// Mitsubishi GX Works2 project: L系列PLC与BD45XX通信例程   PLC: L02

PROGRAM MAIN
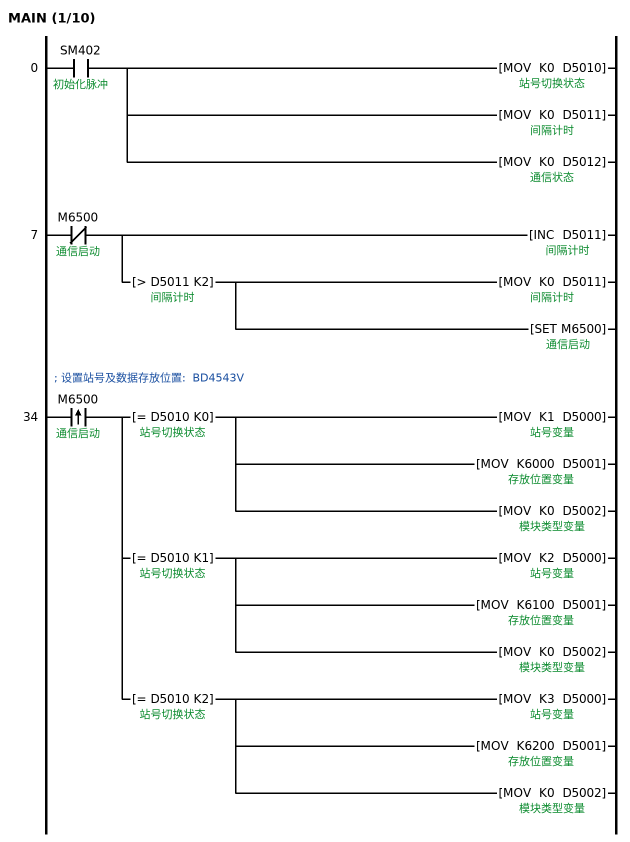
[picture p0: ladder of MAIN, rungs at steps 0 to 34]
0     LD      SM402  ; 初始化脉冲
      MOV     K0 D5010  ; 站号切换状态
      MOV     K0 D5011  ; 间隔计时
      MOV     K0 D5012  ; 通信状态
7     LDI     M6500  ; 通信启动
      INC     D5011
      AND>    D5011 K2  ; 间隔计时
      MOV     K0 D5011
      SET     M6500  ; 通信启动
; 设置站号及数据存放位置:  BD4543V
34    LDP     M6500  ; 通信启动
      MPS
      AND=    D5010 K0  ; 站号切换状态
      MOV     K1 D5000  ; 站号变量
      MOV     K6000 D5001  ; 存放位置变量
      MOV     K0 D5002  ; 模块类型变量
      MRD
      AND=    D5010 K1  ; 站号切换状态
      MOV     K2 D5000
      MOV     K6100 D5001
      MOV     K0 D5002
      MPP
      AND=    D5010 K2  ; 站号切换状态
      MOV     K3 D5000
      MOV     K6200 D5001
      MOV     K0 D5002
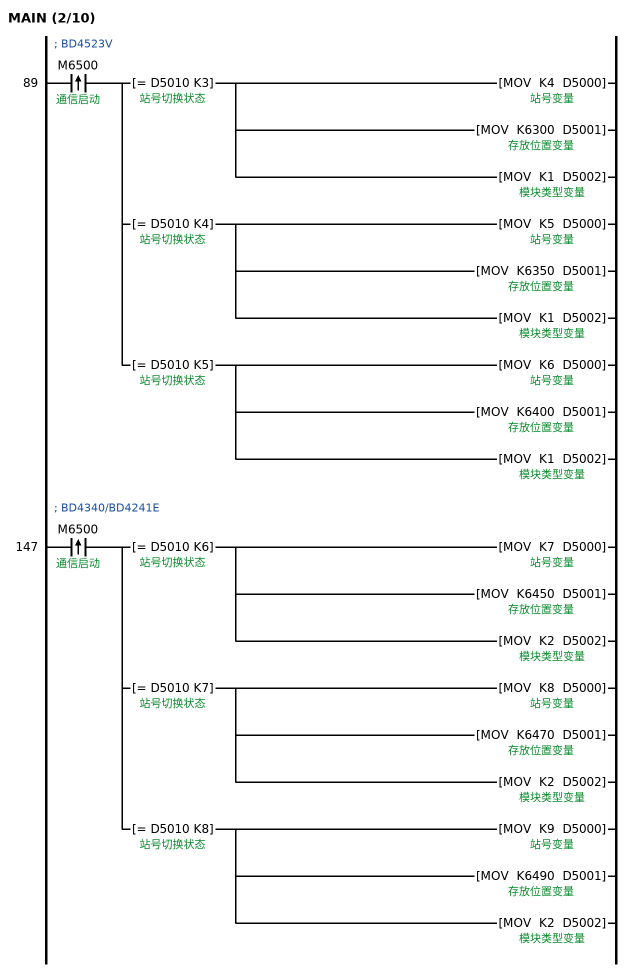
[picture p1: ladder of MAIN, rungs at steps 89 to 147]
; BD4523V
89    LDP     M6500  ; 通信启动
      MPS
      AND=    D5010 K3  ; 站号切换状态
      MOV     K4 D5000
      MOV     K6300 D5001
      MOV     K1 D5002
      MRD
      AND=    D5010 K4  ; 站号切换状态
      MOV     K5 D5000
      MOV     K6350 D5001
      MOV     K1 D5002
      MPP
      AND=    D5010 K5  ; 站号切换状态
      MOV     K6 D5000
      MOV     K6400 D5001
      MOV     K1 D5002
; BD4340/BD4241E
147   LDP     M6500  ; 通信启动
      MPS
      AND=    D5010 K6  ; 站号切换状态
      MOV     K7 D5000
      MOV     K6450 D5001
      MOV     K2 D5002
      MRD
      AND=    D5010 K7  ; 站号切换状态
      MOV     K8 D5000
      MOV     K6470 D5001
      MOV     K2 D5002
      MPP
      AND=    D5010 K8  ; 站号切换状态
      MOV     K9 D5000
      MOV     K6490 D5001
      MOV     K2 D5002
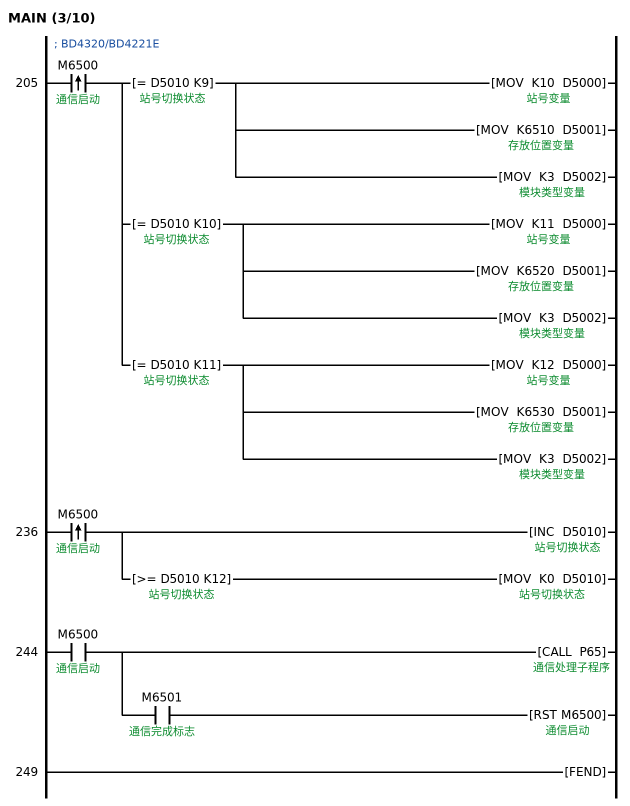
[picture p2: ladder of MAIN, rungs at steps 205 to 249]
; BD4320/BD4221E
205   LDP     M6500  ; 通信启动
      MPS
      AND=    D5010 K9  ; 站号切换状态
      MOV     K10 D5000
      MOV     K6510 D5001
      MOV     K3 D5002
      MRD
      AND=    D5010 K10  ; 站号切换状态
      MOV     K11 D5000
      MOV     K6520 D5001
      MOV     K3 D5002
      MPP
      AND=    D5010 K11  ; 站号切换状态
      MOV     K12 D5000
      MOV     K6530 D5001
      MOV     K3 D5002
236   LDP     M6500  ; 通信启动
      INC     D5010
      AND>=   D5010 K12  ; 站号切换状态
      MOV     K0 D5010
244   LD      M6500  ; 通信启动
      CALL    P65  ; 通信处理子程序
      AND     M6501  ; 通信完成标志
      RST     M6500  ; 通信启动
249   FEND
      P65
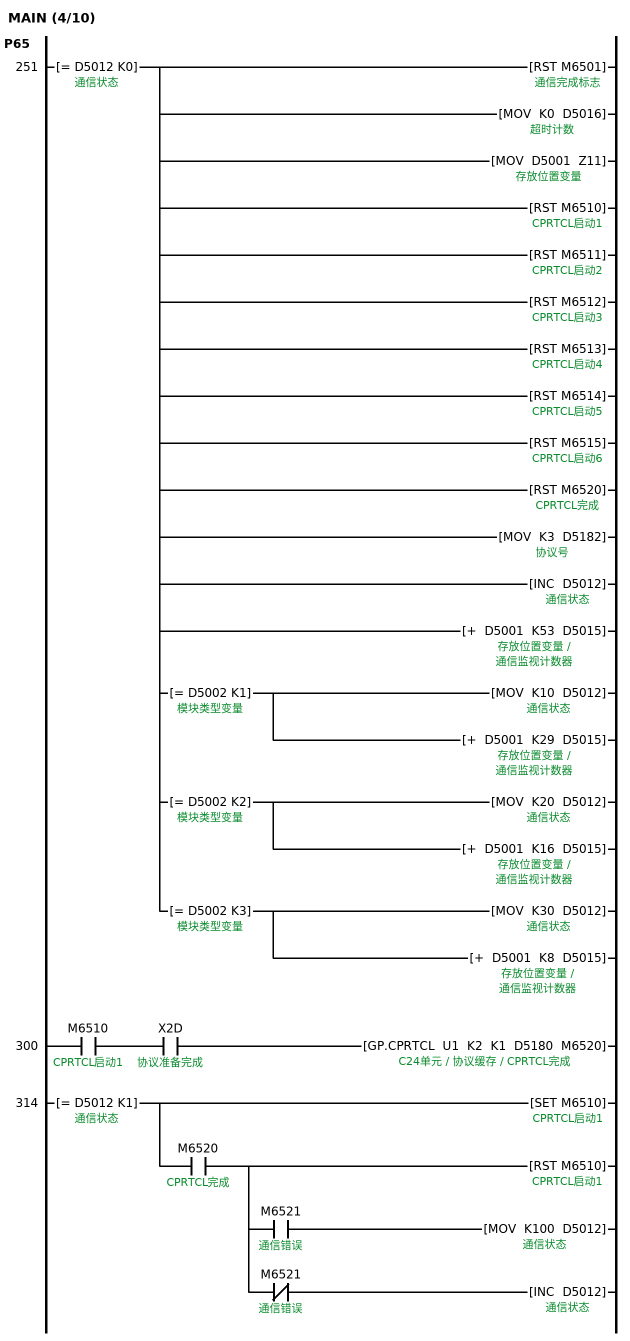
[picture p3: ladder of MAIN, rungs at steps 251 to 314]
251   LD=     D5012 K0  ; 通信状态
      RST     M6501  ; 通信完成标志
      MOV     K0 D5016  ; 超时计数
      MOV     D5001 Z11
      RST     M6510  ; CPRTCL启动1
      RST     M6511  ; CPRTCL启动2
      RST     M6512  ; CPRTCL启动3
      RST     M6513  ; CPRTCL启动4
      RST     M6514  ; CPRTCL启动5
      RST     M6515  ; CPRTCL启动6
      RST     M6520  ; CPRTCL完成
      MOV     K3 D5182  ; 协议号
      INC     D5012
      +       D5001 K53 D5015  ; 通信监视计数器
      MPS
      AND=    D5002 K1  ; 模块类型变量
      MOV     K10 D5012
      +       D5001 K29 D5015
      MRD
      AND=    D5002 K2  ; 模块类型变量
      MOV     K20 D5012
      +       D5001 K16 D5015
      MPP
      AND=    D5002 K3  ; 模块类型变量
      MOV     K30 D5012
      +       D5001 K8 D5015
300   LD      M6510  ; CPRTCL启动1
      AND     X2D  ; 协议准备完成
      GP.CPRTCL U1 K2 K1 D5180 M6520  ; C24单元 / 协议缓存
314   LD=     D5012 K1  ; 通信状态
      SET     M6510  ; CPRTCL启动1
      AND     M6520  ; CPRTCL完成
      RST     M6510  ; CPRTCL启动1
      MPS
      AND     M6521  ; 通信错误
      MOV     K100 D5012
      MPP
      ANI     M6521  ; 通信错误
      INC     D5012
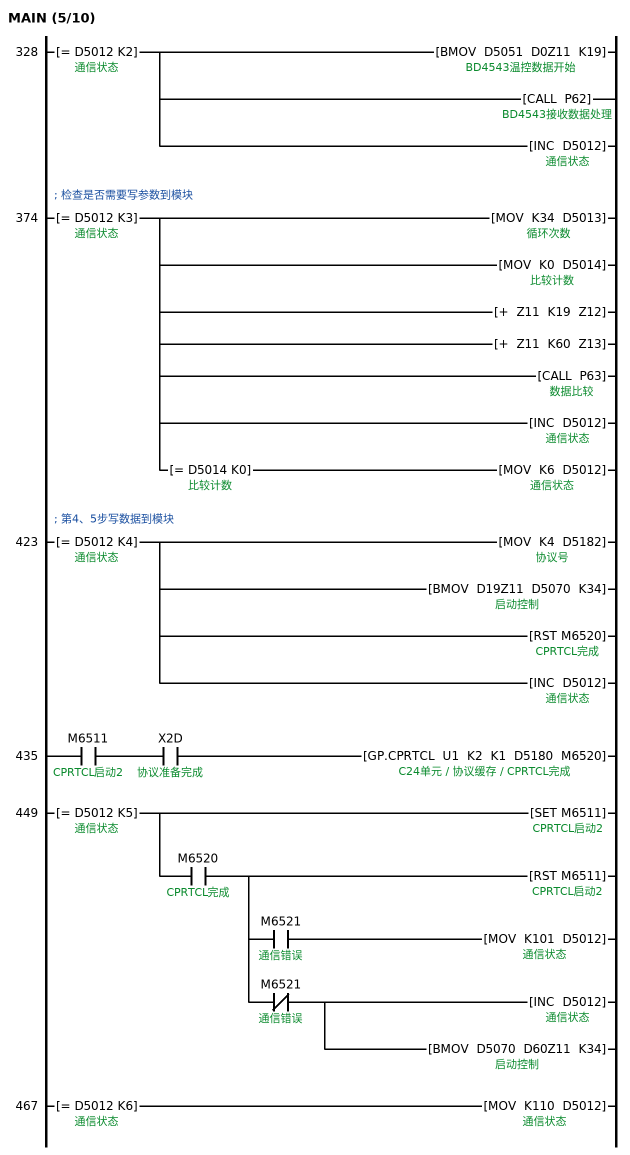
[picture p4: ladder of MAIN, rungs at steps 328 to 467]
328   LD=     D5012 K2  ; 通信状态
      BMOV    D5051 D0Z11 K19  ; BD4543温控数据开始
        [note] 数据处理
      CALL    P62  ; BD4543接收数据处理
      INC     D5012
; 检查是否需要写参数到模块
374   LD=     D5012 K3  ; 通信状态
      MOV     K34 D5013  ; 循环次数
      MOV     K0 D5014  ; 比较计数
      +       Z11 K19 Z12
      +       Z11 K60 Z13
      CALL    P63  ; 数据比较
      INC     D5012
      AND=    D5014 K0  ; 比较计数
      MOV     K6 D5012
; 第4、5步写数据到模块
423   LD=     D5012 K4  ; 通信状态
      MOV     K4 D5182
      BMOV    D19Z11 D5070 K34  ; 启动控制
      RST     M6520  ; CPRTCL完成
      INC     D5012
435   LD      M6511  ; CPRTCL启动2
      AND     X2D  ; 协议准备完成
      GP.CPRTCL U1 K2 K1 D5180 M6520
449   LD=     D5012 K5  ; 通信状态
      SET     M6511  ; CPRTCL启动2
      AND     M6520  ; CPRTCL完成
      RST     M6511  ; CPRTCL启动2
      MPS
      AND     M6521  ; 通信错误
      MOV     K101 D5012
      MPP
      ANI     M6521  ; 通信错误
      INC     D5012
      BMOV    D5070 D60Z11 K34
467   LD=     D5012 K6  ; 通信状态
      MOV     K110 D5012
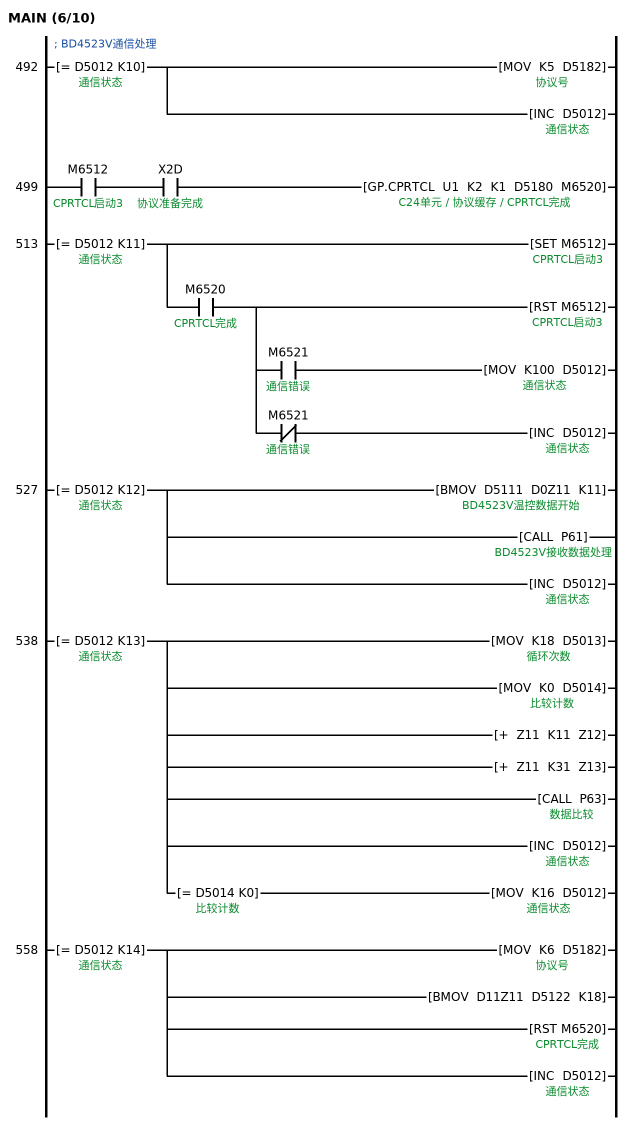
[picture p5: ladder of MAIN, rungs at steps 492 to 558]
; BD4523V通信处理
492   LD=     D5012 K10  ; 通信状态
      MOV     K5 D5182
      INC     D5012
499   LD      M6512  ; CPRTCL启动3
      AND     X2D  ; 协议准备完成
      GP.CPRTCL U1 K2 K1 D5180 M6520
513   LD=     D5012 K11  ; 通信状态
      SET     M6512  ; CPRTCL启动3
      AND     M6520  ; CPRTCL完成
      RST     M6512  ; CPRTCL启动3
      MPS
      AND     M6521  ; 通信错误
      MOV     K100 D5012
      MPP
      ANI     M6521  ; 通信错误
      INC     D5012
527   LD=     D5012 K12  ; 通信状态
      BMOV    D5111 D0Z11 K11  ; BD4523V温控数据开始
      CALL    P61  ; BD4523V接收数据处理
      INC     D5012
538   LD=     D5012 K13  ; 通信状态
      MOV     K18 D5013
      MOV     K0 D5014
      +       Z11 K11 Z12
      +       Z11 K31 Z13
      CALL    P63
      INC     D5012
      AND=    D5014 K0  ; 比较计数
      MOV     K16 D5012
558   LD=     D5012 K14  ; 通信状态
      MOV     K6 D5182
      BMOV    D11Z11 D5122 K18
      RST     M6520  ; CPRTCL完成
      INC     D5012
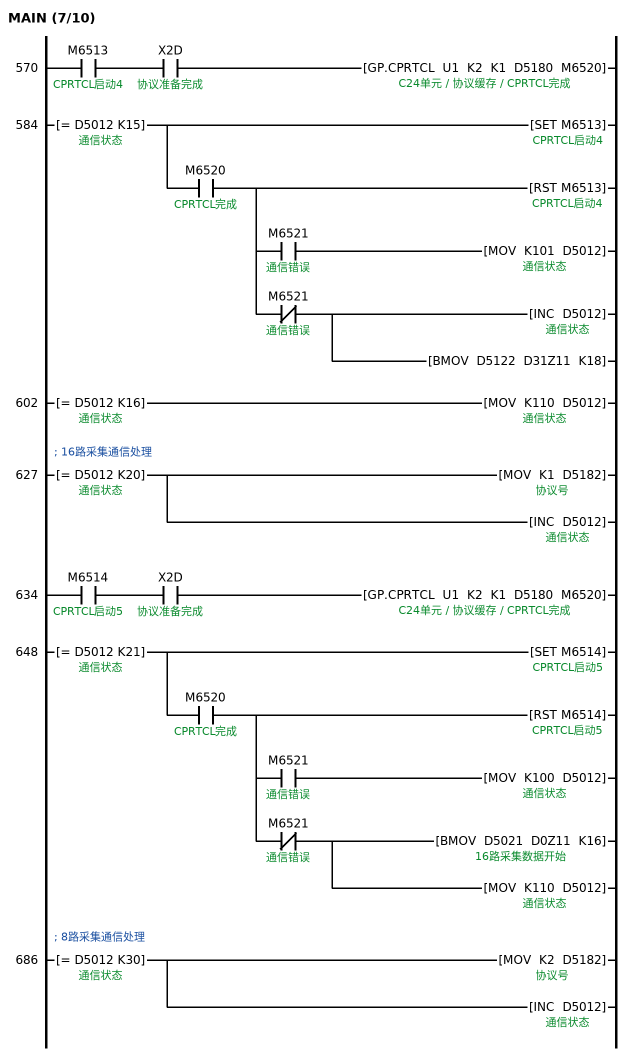
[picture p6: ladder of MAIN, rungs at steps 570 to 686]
570   LD      M6513  ; CPRTCL启动4
      AND     X2D  ; 协议准备完成
      GP.CPRTCL U1 K2 K1 D5180 M6520
584   LD=     D5012 K15  ; 通信状态
      SET     M6513  ; CPRTCL启动4
      AND     M6520  ; CPRTCL完成
      RST     M6513  ; CPRTCL启动4
      MPS
      AND     M6521  ; 通信错误
      MOV     K101 D5012
      MPP
      ANI     M6521  ; 通信错误
      INC     D5012
      BMOV    D5122 D31Z11 K18
602   LD=     D5012 K16  ; 通信状态
      MOV     K110 D5012
; 16路采集通信处理
627   LD=     D5012 K20  ; 通信状态
      MOV     K1 D5182
      INC     D5012
634   LD      M6514  ; CPRTCL启动5
      AND     X2D  ; 协议准备完成
      GP.CPRTCL U1 K2 K1 D5180 M6520
648   LD=     D5012 K21  ; 通信状态
      SET     M6514  ; CPRTCL启动5
      AND     M6520  ; CPRTCL完成
      RST     M6514  ; CPRTCL启动5
      MPS
      AND     M6521  ; 通信错误
      MOV     K100 D5012
      MPP
      ANI     M6521  ; 通信错误
      BMOV    D5021 D0Z11 K16  ; 16路采集数据开始
      MOV     K110 D5012
; 8路采集通信处理
686   LD=     D5012 K30  ; 通信状态
      MOV     K2 D5182
      INC     D5012
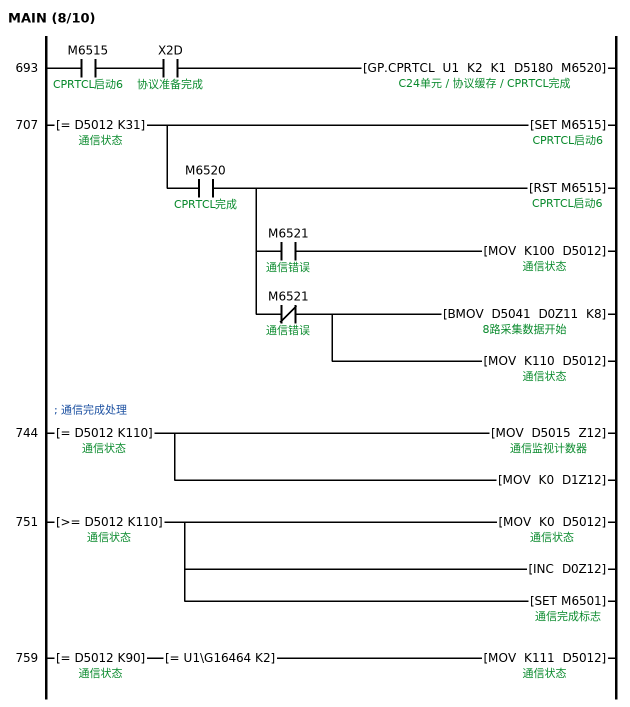
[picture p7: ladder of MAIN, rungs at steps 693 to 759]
693   LD      M6515  ; CPRTCL启动6
      AND     X2D  ; 协议准备完成
      GP.CPRTCL U1 K2 K1 D5180 M6520
707   LD=     D5012 K31  ; 通信状态
      SET     M6515  ; CPRTCL启动6
      AND     M6520  ; CPRTCL完成
      RST     M6515  ; CPRTCL启动6
      MPS
      AND     M6521  ; 通信错误
      MOV     K100 D5012
      MPP
      ANI     M6521  ; 通信错误
      BMOV    D5041 D0Z11 K8  ; 8路采集数据开始
      MOV     K110 D5012
; 通信完成处理
744   LD=     D5012 K110  ; 通信状态
      MOV     D5015 Z12
      MOV     K0 D1Z12
751   LD>=    D5012 K110  ; 通信状态
      MOV     K0 D5012
      INC     D0Z12
      SET     M6501  ; 通信完成标志
759   LD=     D5012 K90  ; 通信状态
      AND=    U1\G16464 K2
      MOV     K111 D5012
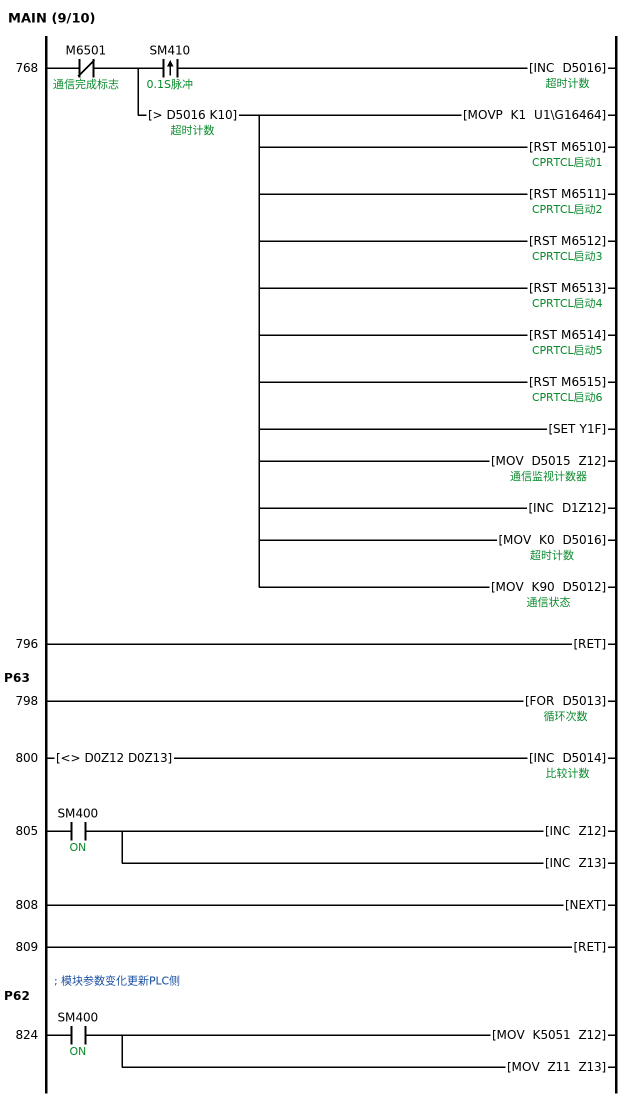
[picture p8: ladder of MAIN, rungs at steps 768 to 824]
768   LDI     M6501  ; 通信完成标志
      MPS
      ANDP    SM410  ; 0.1S脉冲
      INC     D5016
      MPP
      AND>    D5016 K10  ; 超时计数
      MOVP    K1 U1\G16464
      RST     M6510  ; CPRTCL启动1
      RST     M6511  ; CPRTCL启动2
      RST     M6512  ; CPRTCL启动3
      RST     M6513  ; CPRTCL启动4
      RST     M6514  ; CPRTCL启动5
      RST     M6515  ; CPRTCL启动6
      SET     Y1F
      MOV     D5015 Z12
      INC     D1Z12
      MOV     K0 D5016
      MOV     K90 D5012
796   RET
      P63
798   FOR     D5013
800   LD<>    D0Z12 D0Z13
      INC     D5014
805   LD      SM400  ; ON
      INC     Z12
      INC     Z13
808   NEXT
809   RET
; 模块参数变化更新PLC侧
      P62
824   LD      SM400  ; ON
      MOV     K5051 Z12
      MOV     Z11 Z13
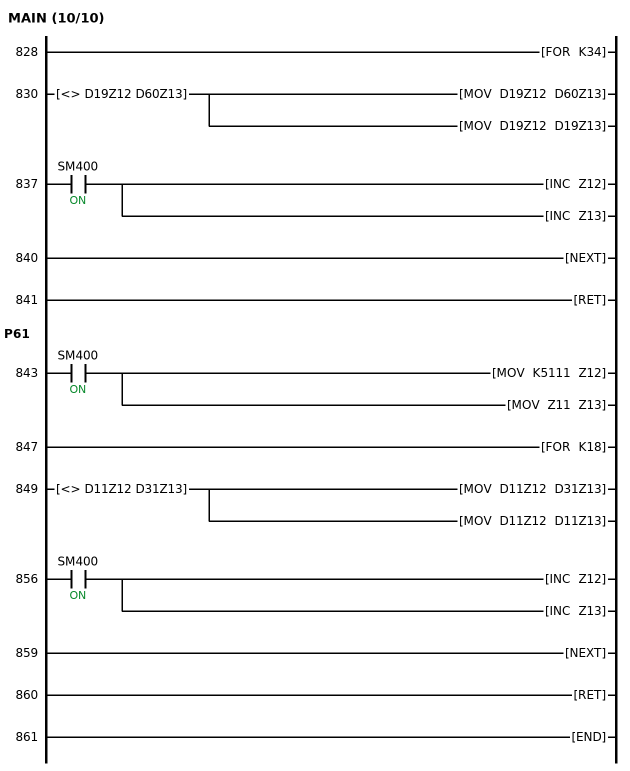
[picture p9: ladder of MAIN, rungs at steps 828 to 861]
828   FOR     K34
830   LD<>    D19Z12 D60Z13
      MOV     D19Z12 D60Z13
      MOV     D19Z12 D19Z13
837   LD      SM400  ; ON
      INC     Z12
      INC     Z13
840   NEXT
841   RET
      P61
843   LD      SM400  ; ON
      MOV     K5111 Z12
      MOV     Z11 Z13
847   FOR     K18
849   LD<>    D11Z12 D31Z13
      MOV     D11Z12 D31Z13
      MOV     D11Z12 D11Z13
856   LD      SM400  ; ON
      INC     Z12
      INC     Z13
859   NEXT
860   RET
861   END
END_PROGRAM

// device comments not shown above
D48  ; 通信故障计数
M6516  ; CPRTCL启动7
M6517  ; CPRTCL启动8
Y0F  ; 出错清除
